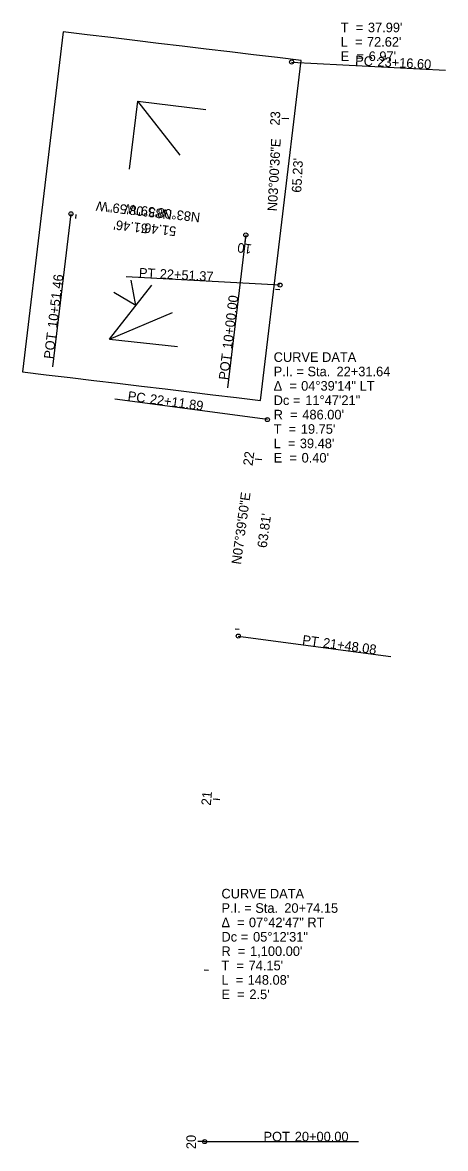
# Model space of a CAD drawing. Extents: x 1564698 to 1565044, y 636021 to 637179.
# Drawn here: x 1564734 to 1564857.6, y 636020.9 to 636349.8 of the extents above; entities that cross this region are included whole.
import ezdxf

# ---------------------------------------------------------------- set-up
doc = ezdxf.new("R2010")
doc.units = 0
for name, color, linetype in [('Default', 7, 'Continuous'), ('GE_P_Alignment_1000_Bearings', 7, 'Continuous'), ('GE_P_Alignment_1000_Cardinal_Points', 7, 'Continuous'), ('GE_P_Alignment_1000_Curve_Data', 7, 'Continuous'), ('GE_P_Alignment_1000_Distances', 7, 'Continuous'), ('GE_P_Alignment_1000_Stations', 7, 'Continuous'), ('GE_P_Alignment_100_Bearings', 7, 'Continuous'), ('GE_P_Alignment_100_Cardinal_Points', 7, 'Continuous'), ('GE_P_Alignment_100_Curve_Data', 7, 'Continuous'), ('GE_P_Alignment_100_Distances', 7, 'Continuous'), ('GE_P_Alignment_100_Stations', 7, 'Continuous'), ('GE_P_Alignment_500_Bearings', 7, 'Continuous'), ('GE_P_Alignment_500_Cardinal_Points', 7, 'Continuous'), ('GE_P_Alignment_500_Curve_Data', 7, 'Continuous'), ('GE_P_Alignment_500_Distances', 7, 'Continuous'), ('GE_P_Alignment_500_Stations', 7, 'Continuous'), ('SH_Named_Boundary', 7, 'Continuous')]:
    doc.layers.add(name, color=color, linetype=linetype)

msp = doc.modelspace()

# ---------------------------------------------------------------- linework, layer by layer
at = {"layer": 'Default'}
for p, q in [((1564765.29, 636306.96), (1564767.67, 636326.81)), ((1564767.67, 636326.81), (1564787.53, 636324.43)), ((1564780.03, 636311.09), (1564767.67, 636326.81)), ((1564759.42, 636257.3), (1564771.74, 636273.05)), ((1564767.12, 636267.15), (1564765.74, 636274.52)), ((1564767.12, 636267.15), (1564760.67, 636270.97)), ((1564759.42, 636257.3), (1564777.84, 636265.1)), ((1564759.42, 636257.3), (1564779.31, 636255.18))]:
    msp.add_line(p, q, dxfattribs=at)
at = {"layer": 'GE_P_Alignment_1000_Cardinal_Points'}
for p, q in [((1564748.15, 636293.91), (1564742.78, 636249.23)), ((1564799.24, 636287.77), (1564793.87, 636243.09))]:
    msp.add_line(p, q, dxfattribs=at)
for centre in [(1564748.15, 636293.91), (1564799.24, 636287.77)]:
    msp.add_circle(centre, 0.6, dxfattribs=at)
at = {"layer": 'GE_P_Alignment_1000_Stations'}
for p, q in [((1564812.64, 636338.27), (1564857.58, 636335.9)), ((1564799.24, 636287.77), (1564799, 636285.78)), ((1564809.22, 636273.12), (1564764.28, 636275.49)), ((1564805.55, 636233.83), (1564760.95, 636239.83)), ((1564797.04, 636170.59), (1564841.64, 636164.59)), ((1564787.21, 636022.95), (1564785.21, 636022.94)), ((1564787.21, 636022.95), (1564832.21, 636022.99))]:
    msp.add_line(p, q, dxfattribs=at)
for centre in [(1564812.64, 636338.27), (1564809.22, 636273.12), (1564805.55, 636233.83), (1564797.04, 636170.59), (1564787.21, 636022.95)]:
    msp.add_circle(centre, 0.6, dxfattribs=at)
at = {"layer": 'GE_P_Alignment_100_Cardinal_Points'}
for p, q in [((1564748.15, 636293.91), (1564742.78, 636249.23)), ((1564799.24, 636287.77), (1564793.87, 636243.09))]:
    msp.add_line(p, q, dxfattribs=at)
for centre in [(1564748.15, 636293.91), (1564799.24, 636287.77)]:
    msp.add_circle(centre, 0.6, dxfattribs=at)
at = {"layer": 'GE_P_Alignment_100_Stations'}
for p, q in [((1564812.64, 636338.27), (1564857.58, 636335.9)), ((1564811.77, 636321.69), (1564809.78, 636321.79)), ((1564749.6, 636293.73), (1564749.45, 636292.54)), ((1564799.24, 636287.77), (1564799, 636285.78)), ((1564809.22, 636273.12), (1564764.28, 636275.49)), ((1564809.15, 636271.76), (1564807.95, 636271.82)), ((1564805.55, 636233.83), (1564760.95, 636239.83)), ((1564803.96, 636222.04), (1564801.98, 636222.31)), ((1564797.29, 636172.49), (1564796.1, 636172.65)), ((1564797.04, 636170.59), (1564841.64, 636164.59)), ((1564791.67, 636122.81), (1564789.68, 636122.99)), ((1564788.31, 636072.93), (1564787.11, 636072.98)), ((1564787.21, 636022.95), (1564785.21, 636022.94)), ((1564787.21, 636022.95), (1564832.21, 636022.99))]:
    msp.add_line(p, q, dxfattribs=at)
for centre in [(1564812.64, 636338.27), (1564809.22, 636273.12), (1564805.55, 636233.83), (1564797.04, 636170.59), (1564787.21, 636022.95)]:
    msp.add_circle(centre, 0.6, dxfattribs=at)
at = {"layer": 'GE_P_Alignment_500_Cardinal_Points'}
for p, q in [((1564748.15, 636293.91), (1564742.78, 636249.23)), ((1564799.24, 636287.77), (1564793.87, 636243.09))]:
    msp.add_line(p, q, dxfattribs=at)
for centre in [(1564748.15, 636293.91), (1564799.24, 636287.77)]:
    msp.add_circle(centre, 0.6, dxfattribs=at)
at = {"layer": 'GE_P_Alignment_500_Stations'}
for p, q in [((1564812.64, 636338.27), (1564857.58, 636335.9)), ((1564811.77, 636321.69), (1564810.57, 636321.75)), ((1564799.24, 636287.77), (1564799, 636285.78)), ((1564809.22, 636273.12), (1564764.28, 636275.49)), ((1564805.55, 636233.83), (1564760.95, 636239.83)), ((1564803.96, 636222.04), (1564802.77, 636222.2)), ((1564797.04, 636170.59), (1564841.64, 636164.59)), ((1564791.67, 636122.81), (1564790.47, 636122.92)), ((1564787.21, 636022.95), (1564785.21, 636022.94)), ((1564787.21, 636022.95), (1564832.21, 636022.99))]:
    msp.add_line(p, q, dxfattribs=at)
for centre in [(1564812.64, 636338.27), (1564809.22, 636273.12), (1564805.55, 636233.83), (1564797.04, 636170.59), (1564787.21, 636022.95)]:
    msp.add_circle(centre, 0.6, dxfattribs=at)
at = {"layer": 'SH_Named_Boundary'}
msp.add_lwpolyline([(1564803.5, 636239.43), (1564815.43, 636338.71), (1564808.48, 636339.55), (1564801.53, 636340.38), (1564794.58, 636341.22), (1564787.63, 636342.05), (1564780.68, 636342.89), (1564773.73, 636343.72), (1564766.78, 636344.56), (1564759.83, 636345.39), (1564752.88, 636346.23), (1564745.93, 636347.06), (1564734, 636247.78), (1564740.95, 636246.94), (1564747.9, 636246.11), (1564754.85, 636245.27), (1564761.8, 636244.44), (1564768.75, 636243.6), (1564775.7, 636242.77), (1564782.65, 636241.93), (1564789.6, 636241.1), (1564796.55, 636240.26)], close=True, dxfattribs=at)

# ---------------------------------------------------------------- texts
at = {"layer": 'GE_P_Alignment_1000_Bearings'}
msp.add_text('N83°08\'59"W', height=2.8, rotation=173.1496, dxfattribs=at).set_placement((1564786.05, 636294.19))
at = {"layer": 'GE_P_Alignment_1000_Cardinal_Points'}
for s, p in [('10+51.46', (1564744.08, 636260.49)), ('10+00.00', (1564795.18, 636254.35)), ('POT', (1564743, 636251.42)), ('POT', (1564794.09, 636245.29))]:
    msp.add_text(s, height=2.8, rotation=83.1496, dxfattribs=at).set_placement(p)
at = {"layer": 'GE_P_Alignment_1000_Curve_Data'}
for s, p in [('T  = ', (1564826.98, 636346.96)), ("37.99'", (1564834.92, 636346.96)), ('L  = ', (1564826.98, 636342.76)), ("72.62'", (1564834.63, 636342.76)), ('E  = ', (1564826.98, 636338.56)), ("6.97'", (1564835.14, 636338.56)), ('CURVE DATA', (1564807.38, 636250.68)), ('P.I. = Sta. ', (1564807.38, 636246.48)), ('22+31.64', (1564825.75, 636246.48)), ('Δ  = ', (1564807.38, 636242.28)), ('04°39\'14" LT', (1564815.41, 636242.28)), ('Dc = ', (1564807.38, 636238.08)), ('11°47\'21"', (1564816.62, 636238.08)), ('R  = ', (1564807.38, 636233.88)), ("486.00'", (1564815.75, 636233.88)), ('T  = ', (1564807.38, 636229.68)), ("19.75'", (1564815.32, 636229.68)), ('L  = ', (1564807.38, 636225.48)), ("39.48'", (1564815.03, 636225.48)), ('E  = ', (1564807.38, 636221.28)), ("0.40'", (1564815.54, 636221.28)), ('CURVE DATA', (1564792.13, 636093.97)), ('P.I. = Sta. ', (1564792.13, 636089.77)), ('20+74.15', (1564810.49, 636089.77)), ('Δ  = ', (1564792.13, 636085.57)), ('07°42\'47" RT', (1564800.15, 636085.57)), ('Dc = ', (1564792.13, 636081.37)), ('05°12\'31"', (1564801.36, 636081.37)), ('R  = ', (1564792.13, 636077.17)), ("1,100.00'", (1564800.49, 636077.17)), ('T  = ', (1564792.13, 636072.97)), ("74.15'", (1564800.06, 636072.97)), ('L  = ', (1564792.13, 636068.77)), ("148.08'", (1564799.77, 636068.77)), ('E  = ', (1564792.13, 636064.57)), ("2.5'", (1564800.28, 636064.57))]:
    msp.add_text(s, height=2.8, dxfattribs=at).set_placement(p)
for s, rotation, p in [('N03°00\'36"E', 86.99, (1564808.35, 636294.63)), ("65.23'", 86.99, (1564815.44, 636300.05)), ('N07°39\'50"E', 82.3361, (1564797.82, 636191.39)), ("63.81'", 82.3361, (1564805.33, 636196.22))]:
    msp.add_text(s, height=2.8, rotation=rotation, dxfattribs=at).set_placement(p)
at = {"layer": 'GE_P_Alignment_1000_Distances'}
msp.add_text("51.46'", height=2.8, rotation=173.1496, dxfattribs=at).set_placement((1564779.05, 636290.15))
at = {"layer": 'GE_P_Alignment_1000_Stations'}
for s, rotation, p in [('PC', 356.99, (1564831.13, 636337.34)), ('23+16.60', 356.99, (1564837.65, 636337)), ('10', 173.1496, (1564801.11, 636284.98)), ('PT', 356.99, (1564767.95, 636275.34)), ('22+51.37', 356.99, (1564774.03, 636275.02)), ('PC', 352.3361, (1564764.61, 636239.39)), ('22+11.89', 352.3361, (1564771.07, 636238.52)), ('PT', 352.3361, (1564815.61, 636168.14)), ('21+48.08', 352.3361, (1564821.64, 636167.33)), ('POT', 0.0491, (1564804.42, 636023.01)), ('20+00.00', 0.0491, (1564813.55, 636023.02)), ('20', 90.0491, (1564784.67, 636020.75))]:
    msp.add_text(s, height=2.8, rotation=rotation, dxfattribs=at).set_placement(p)
at = {"layer": 'GE_P_Alignment_100_Bearings'}
msp.add_text('N83°08\'59"W', height=2.8, rotation=173.1496, dxfattribs=at).set_placement((1564777.8, 636294.99))
at = {"layer": 'GE_P_Alignment_100_Cardinal_Points'}
for s, p in [('10+51.46', (1564744.08, 636260.49)), ('10+00.00', (1564795.18, 636254.35)), ('POT', (1564743, 636251.42)), ('POT', (1564794.09, 636245.29))]:
    msp.add_text(s, height=2.8, rotation=83.1496, dxfattribs=at).set_placement(p)
at = {"layer": 'GE_P_Alignment_100_Curve_Data'}
for s, p in [('T  = ', (1564826.98, 636346.96)), ("37.99'", (1564834.92, 636346.96)), ('L  = ', (1564826.98, 636342.76)), ("72.62'", (1564834.63, 636342.76)), ('E  = ', (1564826.98, 636338.56)), ("6.97'", (1564835.14, 636338.56)), ('CURVE DATA', (1564807.38, 636250.68)), ('P.I. = Sta. ', (1564807.38, 636246.48)), ('22+31.64', (1564825.75, 636246.48)), ('Δ  = ', (1564807.38, 636242.28)), ('04°39\'14" LT', (1564815.41, 636242.28)), ('Dc = ', (1564807.38, 636238.08)), ('11°47\'21"', (1564816.62, 636238.08)), ('R  = ', (1564807.38, 636233.88)), ("486.00'", (1564815.75, 636233.88)), ('T  = ', (1564807.38, 636229.68)), ("19.75'", (1564815.32, 636229.68)), ('L  = ', (1564807.38, 636225.48)), ("39.48'", (1564815.03, 636225.48)), ('E  = ', (1564807.38, 636221.28)), ("0.40'", (1564815.54, 636221.28)), ('CURVE DATA', (1564792.13, 636093.97)), ('P.I. = Sta. ', (1564792.13, 636089.77)), ('20+74.15', (1564810.49, 636089.77)), ('Δ  = ', (1564792.13, 636085.57)), ('07°42\'47" RT', (1564800.15, 636085.57)), ('Dc = ', (1564792.13, 636081.37)), ('05°12\'31"', (1564801.36, 636081.37)), ('R  = ', (1564792.13, 636077.17)), ("1,100.00'", (1564800.49, 636077.17)), ('T  = ', (1564792.13, 636072.97)), ("74.15'", (1564800.06, 636072.97)), ('L  = ', (1564792.13, 636068.77)), ("148.08'", (1564799.77, 636068.77)), ('E  = ', (1564792.13, 636064.57)), ("2.5'", (1564800.28, 636064.57))]:
    msp.add_text(s, height=2.8, dxfattribs=at).set_placement(p)
for s, rotation, p in [('N03°00\'36"E', 86.99, (1564808.35, 636294.63)), ("65.23'", 86.99, (1564815.44, 636300.05)), ('N07°39\'50"E', 82.3361, (1564797.82, 636191.39)), ("63.81'", 82.3361, (1564805.33, 636196.22))]:
    msp.add_text(s, height=2.8, rotation=rotation, dxfattribs=at).set_placement(p)
at = {"layer": 'GE_P_Alignment_100_Distances'}
msp.add_text("51.46'", height=2.8, rotation=173.1496, dxfattribs=at).set_placement((1564770.8, 636290.95))
at = {"layer": 'GE_P_Alignment_100_Stations'}
for s, rotation, p in [('PC', 356.99, (1564831.13, 636337.34)), ('23+16.60', 356.99, (1564837.65, 636337)), ('23', 86.99, (1564809.11, 636319.65)), ('10', 173.1496, (1564801.11, 636284.98)), ('PT', 356.99, (1564767.95, 636275.34)), ('22+51.37', 356.99, (1564774.03, 636275.02)), ('PC', 352.3361, (1564764.61, 636239.39)), ('22+11.89', 352.3361, (1564771.07, 636238.52)), ('22', 82.3361, (1564801.19, 636220.21)), ('PT', 352.3361, (1564815.61, 636168.14)), ('21+48.08', 352.3361, (1564821.64, 636167.33)), ('21', 84.8404, (1564789, 636121.02)), ('POT', 0.0491, (1564804.42, 636023.01)), ('20+00.00', 0.0491, (1564813.55, 636023.02)), ('20', 90.0491, (1564784.67, 636020.75))]:
    msp.add_text(s, height=2.8, rotation=rotation, dxfattribs=at).set_placement(p)
at = {"layer": 'GE_P_Alignment_500_Bearings'}
msp.add_text('N83°08\'59"W', height=2.8, rotation=173.1496, dxfattribs=at).set_placement((1564786.05, 636294.19))
at = {"layer": 'GE_P_Alignment_500_Cardinal_Points'}
for s, p in [('10+51.46', (1564744.08, 636260.49)), ('10+00.00', (1564795.18, 636254.35)), ('POT', (1564743, 636251.42)), ('POT', (1564794.09, 636245.29))]:
    msp.add_text(s, height=2.8, rotation=83.1496, dxfattribs=at).set_placement(p)
at = {"layer": 'GE_P_Alignment_500_Curve_Data'}
for s, p in [('T  = ', (1564826.98, 636346.96)), ("37.99'", (1564834.92, 636346.96)), ('L  = ', (1564826.98, 636342.76)), ("72.62'", (1564834.63, 636342.76)), ('E  = ', (1564826.98, 636338.56)), ("6.97'", (1564835.14, 636338.56)), ('CURVE DATA', (1564807.38, 636250.68)), ('P.I. = Sta. ', (1564807.38, 636246.48)), ('22+31.64', (1564825.75, 636246.48)), ('Δ  = ', (1564807.38, 636242.28)), ('04°39\'14" LT', (1564815.41, 636242.28)), ('Dc = ', (1564807.38, 636238.08)), ('11°47\'21"', (1564816.62, 636238.08)), ('R  = ', (1564807.38, 636233.88)), ("486.00'", (1564815.75, 636233.88)), ('T  = ', (1564807.38, 636229.68)), ("19.75'", (1564815.32, 636229.68)), ('L  = ', (1564807.38, 636225.48)), ("39.48'", (1564815.03, 636225.48)), ('E  = ', (1564807.38, 636221.28)), ("0.40'", (1564815.54, 636221.28)), ('CURVE DATA', (1564792.13, 636093.97)), ('P.I. = Sta. ', (1564792.13, 636089.77)), ('20+74.15', (1564810.49, 636089.77)), ('Δ  = ', (1564792.13, 636085.57)), ('07°42\'47" RT', (1564800.15, 636085.57)), ('Dc = ', (1564792.13, 636081.37)), ('05°12\'31"', (1564801.36, 636081.37)), ('R  = ', (1564792.13, 636077.17)), ("1,100.00'", (1564800.49, 636077.17)), ('T  = ', (1564792.13, 636072.97)), ("74.15'", (1564800.06, 636072.97)), ('L  = ', (1564792.13, 636068.77)), ("148.08'", (1564799.77, 636068.77)), ('E  = ', (1564792.13, 636064.57)), ("2.5'", (1564800.28, 636064.57))]:
    msp.add_text(s, height=2.8, dxfattribs=at).set_placement(p)
for s, rotation, p in [('N03°00\'36"E', 86.99, (1564808.35, 636294.63)), ("65.23'", 86.99, (1564815.44, 636300.05)), ('N07°39\'50"E', 82.3361, (1564797.82, 636191.39)), ("63.81'", 82.3361, (1564805.33, 636196.22))]:
    msp.add_text(s, height=2.8, rotation=rotation, dxfattribs=at).set_placement(p)
at = {"layer": 'GE_P_Alignment_500_Distances'}
msp.add_text("51.46'", height=2.8, rotation=173.1496, dxfattribs=at).set_placement((1564779.05, 636290.15))
at = {"layer": 'GE_P_Alignment_500_Stations'}
for s, rotation, p in [('PC', 356.99, (1564831.13, 636337.34)), ('23+16.60', 356.99, (1564837.65, 636337)), ('10', 173.1496, (1564801.11, 636284.98)), ('PT', 356.99, (1564767.95, 636275.34)), ('22+51.37', 356.99, (1564774.03, 636275.02)), ('PC', 352.3361, (1564764.61, 636239.39)), ('22+11.89', 352.3361, (1564771.07, 636238.52)), ('PT', 352.3361, (1564815.61, 636168.14)), ('21+48.08', 352.3361, (1564821.64, 636167.33)), ('POT', 0.0491, (1564804.42, 636023.01)), ('20+00.00', 0.0491, (1564813.55, 636023.02)), ('20', 90.0491, (1564784.67, 636020.75))]:
    msp.add_text(s, height=2.8, rotation=rotation, dxfattribs=at).set_placement(p)

doc.saveas('drawing.dxf')
